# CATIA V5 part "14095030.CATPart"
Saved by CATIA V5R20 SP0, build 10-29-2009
Part number: 14095030
Definition: NONE
Nomenclature: 14095030
Source: Unknown
Description: 14095030
Bounding box of the stored display mesh (mm): x -15 to 60, y -61.5 to 51.6, z -51.6 to 51.6
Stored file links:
  C:\Users\Utente\Desktop\IO LAVORO\3D X SITO CF\X SITO\PLASTICA\RF2\14095030.CATPart
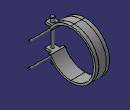
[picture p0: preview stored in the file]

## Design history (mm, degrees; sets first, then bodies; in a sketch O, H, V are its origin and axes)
Body1 "14095030" (main body)
  Solid1: solid without history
